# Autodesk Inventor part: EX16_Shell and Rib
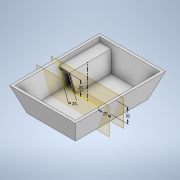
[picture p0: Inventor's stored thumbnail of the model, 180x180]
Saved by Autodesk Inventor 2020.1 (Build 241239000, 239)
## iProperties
Created: 2019-10
Part Number: EX16_Shell and Rib
Material: Generic
Document SubType Name: Modeling
Designer: Synergysoft Dell02
Density: 1 g/cm^3
Appearance: Default
Author: Synergysoft Dell02
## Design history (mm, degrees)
sketch "Sketch1"
  geometry: L1 (50, -75)-(-50, -75); L2 (-50, -75)-(-50, 75); L3 (-50, 75)-(50, 75); L4 (50, 75)-(50, -75); L5 (50, -75)-(-50, 75); L6 (-50, -75)-(50, 75); 1 further point
  constraints: 12 end point, 2 midpoint, 2 parallel, 1 horizontal, 1 perpendicular
  dimensions: "d0" = 100 distance of L2.end L3.end; "d1" = 150 distance of L1.end L2.end
extrude "Extrusion1" new body sketch "Sketch1" distance "d2" = 50; taper "d3" = 20 deg
shell "Shell1" dims "d4" = 5, "d27" = 10
workplane "Work Plane1"
workplane "Work Plane2"
feature "Rib2" dims "d15" = 5, "d16" = 1, "d17" = 0, "d18" = 0, "d19" = 1, "d20" = 1
feature "Rib4" dims "d34" = 10, "d35" = 10, "d36" = 0, "d37" = 0, "d38" = 1, "d39" = 1
workplane "Work Plane3"
sketch "Sketch3"
  geometry: L1 (23.319, 10)-(59.238, 40) reference; 1 further point
feature "Rib5" sketch "Sketch3" dims "d41" = 5, "d42" = 20, "d43" = 0, "d44" = 0, "d45" = 1, "d46" = 1
body "Solid1"
sketch "Sketch2"
  geometry: L1 (-48.319, 10)-(-62.878, 50) reference; L2 (48.319, 10)-(-48.319, 10) reference; L3 (48.319, 10)-(62.878, 50) reference; L4 (-59.238, 40)-(-37.954, 40); L5 (-37.954, 40)-(-27.035, 10); L6 (0, 0)-(0, 79.65); L7 (23.319, 10)-(59.238, 40)
  constraints: 8 end point, 4 point on line, 1 horizontal, 1 parallel, 1 vertical
  dimensions: "d7" = 30 distance between parallel lines of L2 L4; "d8" = 20 distance between parallel lines of L5 L1; "d32" = 25 distance of L2.start L7.start; "d33" = 30 distance from line of L7.end L2
